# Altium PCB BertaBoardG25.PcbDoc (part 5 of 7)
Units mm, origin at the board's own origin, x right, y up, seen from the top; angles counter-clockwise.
Board outline 160 x 160 mm, 4 copper layers (Top, GND Plane, Power Plane, Bottom), stack 1.344 mm thick; 17 components, 112 nets, 2311 pads, 138 vias.
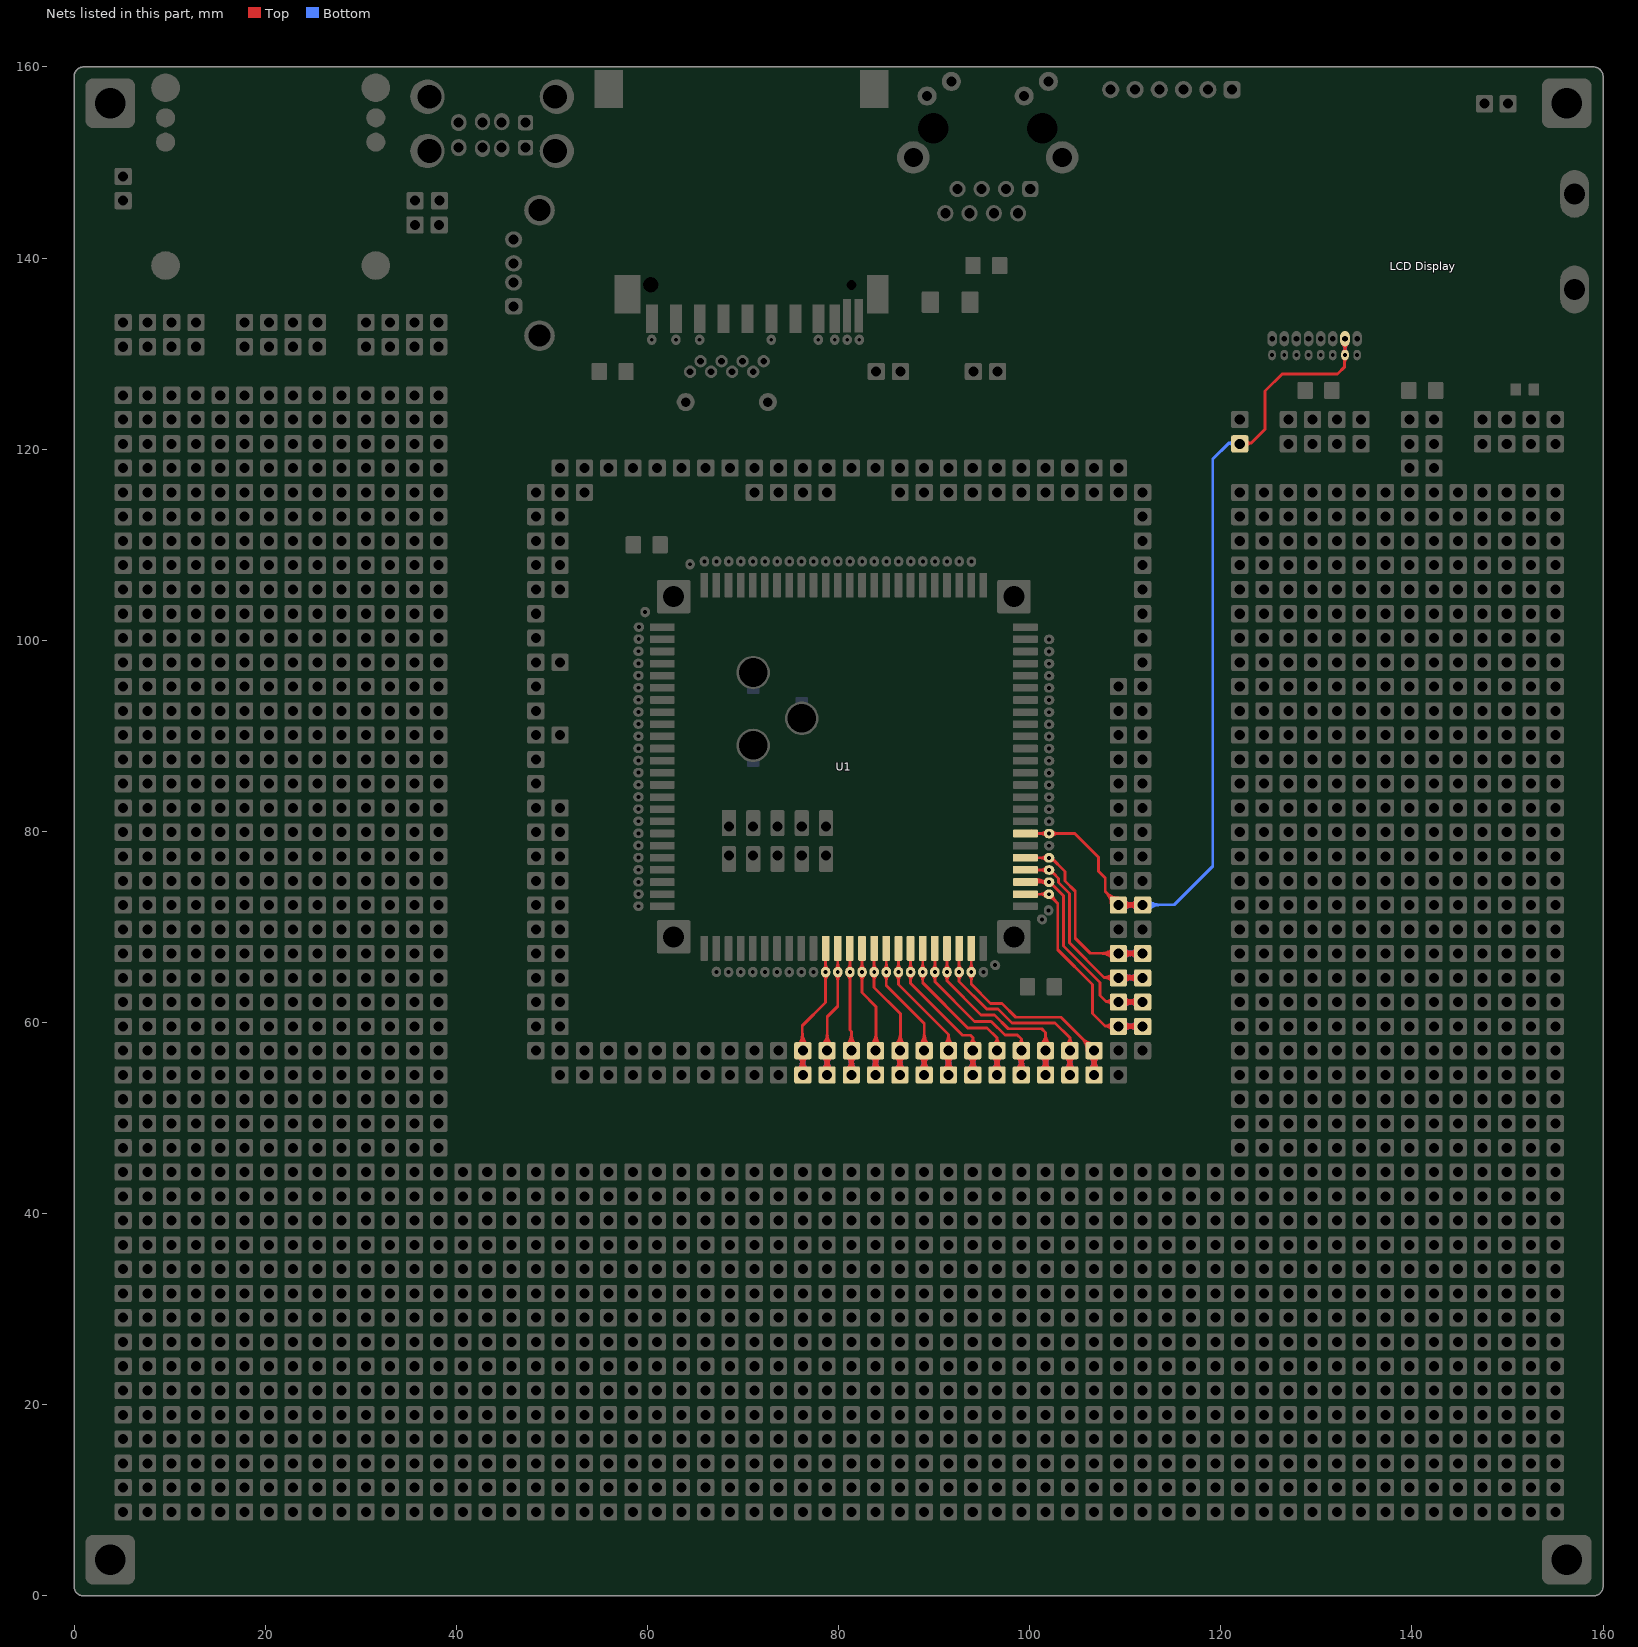
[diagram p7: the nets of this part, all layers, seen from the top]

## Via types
v1: diameter 1.5, hole 0.7, Top to Bottom, tented both sides, 54 vias
v2: diameter 1.1, hole 0.4, Top to Bottom, tented both sides, 49 vias
v3: diameter 1.9, hole 1.05, Top to Bottom, tented both sides, 17 vias
v4: diameter 1.9, hole 1.05, Top to Bottom, 16 vias
v5: diameter 0.9, hole 0.4, Top to Bottom, tented both sides, 2 vias

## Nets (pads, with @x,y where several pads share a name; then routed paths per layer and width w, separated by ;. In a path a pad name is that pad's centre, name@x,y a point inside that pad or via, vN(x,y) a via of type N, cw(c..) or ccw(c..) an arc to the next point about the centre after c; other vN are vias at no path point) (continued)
PA31: "LCD Display.7" pad.0@102.032,79.777 pad.0@109.282,72.3 pad.0@111.822,72.3 pad.0@121.982,120.56 pad.0@132.993,129.853 U1.W18 | length 142.3
  Top w0.3: U1.W18@99.551,79.785 104.716,79.785 107.201,77.3 107.201,75.83 107.901,75.13 107.901,73.72 109.291,72.33 pad.0@111.831,72.33 ; U1.W18@99.992,79.825 ccw(c100.089,79.923) U1.W18@100.089,79.785 ; U1.W18@100.204,80.037 ccw(c100.813,80.647) U1.W18@100.813,79.785 ; 101.119,79.785 cw(c101.119,78.914) pad.0@101.735,79.53 ; 101.155,79.785 ccw(c101.155,80.604) pad.0@101.735,80.025 ; pad.0@102.33,79.53 cw(c102.945,78.914) 102.945,79.785 ; pad.0@102.33,80.025 ccw(c102.909,80.604) 102.909,79.785 ; 107.973,73.647 cw(c106.626,72.3) pad.0@108.532,72.3 ; 108.069,73.552 ccw(c109.282,74.765) pad.0@109.282,73.05 ; pad.0@108.486,73.135 cw(c107.65,72.3) pad.0@108.832,72.3 ; pad.0@108.581,73.04 ccw(c109.282,73.74) pad.0@109.282,72.75 ; pad.0@109.6,71.981 cw(c110.441,71.14) 110.441,72.33 ; pad.0@109.6,72.618 ccw(c110.295,73.313) 110.295,72.33 ; pad.0@109.812,71.769 cw(c111.165,70.416) pad.0@111.165,72.33 ; pad.0@109.812,72.83 ccw(c111.02,74.037) pad.0@111.02,72.33 ; pad.0@109.938,72.33 cw(c109.938,70.416) pad.0@111.291,71.769 ; pad.0@110.084,72.33 ccw(c110.084,74.037) pad.0@111.291,72.83 ; 110.663,72.33 cw(c110.663,71.14) pad.0@111.504,71.981 ; 110.808,72.33 ccw(c110.808,73.313) pad.0@111.504,72.618 ; 110.888,72.365 ccw(c111.027,72.883) pad.0@111.459,72.566 ; pad.0@111.161,72.654 cw(c110.284,73.123) 110.541,72.163 cw(c110.691,71.605) pad.0@111.183,71.907 ; pad.0@111.168,71.932 ccw(c110.167,71.37) 110.464,72.478 ccw(c110.647,73.161) pad.0@111.217,72.743 ; pad.0@122.061,120.63 123.171,120.63 ; pad.0@122.628,120.94 ccw(c123.171,121.26) 123.171,120.63 ; pad.0@122.683,120.293 cw(c123.171,120.107) 123.171,120.63 ; 132.745,131.014 cw(c132.148,130.416) 132.993,130.416 cw(c133.838,130.416) 133.24,131.014 ; pad.0@132.816,129.526 cw(c132.466,129.176) 132.961,129.176 ; pad.0@132.816,130.179 ccw(c132.389,130.606) 132.993,130.606 ccw(c133.596,130.606) pad.0@133.17,130.179 ; 132.961,129.023 cw(c133.673,129.023) pad.0@133.17,129.526 ; pad.0@132.961,130.16 132.961,128.63 132.212,127.881 126.422,127.881 124.63,126.089 124.63,122.089 123.171,120.63 ; pad.0@132.993,130.16 132.993,131.561
  Bottom w0.3: pad.0@109.291,72.33 111.831,72.33 115.131,72.33 119.161,76.36 119.161,118.96 120.831,120.63 ; pad.0@109.6,71.981 cw(c110.441,71.14) 110.441,72.33 ; pad.0@109.6,72.618 ccw(c110.295,73.313) 110.295,72.33 ; pad.0@109.812,71.769 cw(c111.165,70.416) pad.0@111.165,72.33 ; pad.0@109.812,72.83 ccw(c111.02,74.037) pad.0@111.02,72.33 ; pad.0@109.938,72.33 cw(c109.938,70.416) pad.0@111.291,71.769 ; pad.0@110.084,72.33 ccw(c110.084,74.037) pad.0@111.291,72.83 ; 110.663,72.33 cw(c110.663,71.14) pad.0@111.504,71.981 ; 110.808,72.33 ccw(c110.808,73.313) pad.0@111.504,72.618 ; 110.888,72.365 ccw(c111.027,72.883) pad.0@111.459,72.566 ; pad.0@111.161,72.654 cw(c110.284,73.123) 110.541,72.163 cw(c110.691,71.605) pad.0@111.183,71.907 ; pad.0@111.168,71.932 ccw(c110.167,71.37) 110.464,72.478 ccw(c110.647,73.161) pad.0@111.217,72.743 ; pad.0@112.14,71.981 cw(c112.981,71.14) 112.981,72.33 ; pad.0@112.14,72.618 ccw(c112.835,73.313) 112.835,72.33 ; pad.0@112.352,71.769 cw(c113.705,70.416) 113.705,72.33 ; pad.0@112.352,72.83 ccw(c113.56,74.037) 113.56,72.33 ; pad.0@121.273,120.315 ccw(c120.831,120.163) 120.831,120.63 ; pad.0@121.325,120.921 cw(c120.831,121.193) 120.831,120.63 ; pad.0@122.061,120.63 120.831,120.63 ; 132.745,131.014 cw(c132.148,130.416) 132.993,130.416 cw(c133.838,130.416) 133.24,131.014 ; pad.0@132.816,130.179 ccw(c132.389,130.606) 132.993,130.606 ccw(c133.596,130.606) pad.0@133.17,130.179 ; pad.0@132.961,130.16 132.993,130.191 132.993,131.561
PB11: pad.0@102.032,77.237 pad.0@109.282,67.22 pad.0@111.822,67.22 U1.W20 | length 56.9
  Top w0.3: U1.W20@99.551,77.245 102.251,77.245 103.681,75.815 103.681,74.827 104.763,73.745 104.763,68.828 106.341,67.25 pad.0@111.831,67.25 ; U1.W20@99.992,77.285 ccw(c100.089,77.383) U1.W20@100.089,77.245 ; U1.W20@100.204,77.497 ccw(c100.813,78.107) U1.W20@100.813,77.245 ; pad.0@102.063,76.928 pad.0@102.472,76.928 ; 107.398,67.25 cw(c107.398,65.336) pad.0@108.751,66.689 ; 107.544,67.25 ccw(c107.544,68.957) pad.0@108.751,67.75 ; 108.123,67.25 cw(c108.123,66.06) pad.0@108.964,66.901 ; 108.268,67.25 ccw(c108.268,68.233) pad.0@108.964,67.538 ; pad.0@109.6,66.901 cw(c110.441,66.06) 110.441,67.25 ; pad.0@109.6,67.538 ccw(c110.295,68.233) 110.295,67.25 ; pad.0@109.812,66.689 cw(c111.165,65.336) pad.0@111.165,67.25 ; pad.0@109.812,67.75 ccw(c111.02,68.957) pad.0@111.02,67.25 ; pad.0@109.938,67.25 cw(c109.938,65.336) pad.0@111.291,66.689 ; pad.0@110.084,67.25 ccw(c110.084,68.957) pad.0@111.291,67.75 ; 110.663,67.25 cw(c110.663,66.06) pad.0@111.504,66.901 ; 110.808,67.25 ccw(c110.808,68.233) pad.0@111.504,67.538 ; 110.888,67.285 ccw(c111.027,67.803) pad.0@111.459,67.486 ; pad.0@111.161,67.574 cw(c110.284,68.043) 110.541,67.083 cw(c110.691,66.525) pad.0@111.183,66.827 ; pad.0@111.168,66.852 ccw(c110.167,66.29) 110.464,67.398 ccw(c110.647,68.081) pad.0@111.217,67.663 ; 101.119,77.245 cw(c101.119,76.374) 101.735,76.99 ccw(c101.119,76.374) 101.119,77.245 ; 101.155,77.245 ccw(c101.155,78.064) 101.735,77.485 cw(c101.155,78.064) 101.155,77.245
  Bottom w0.3: pad.0@109.291,67.25 pad.0@111.831,67.25 ; pad.0@109.6,66.901 cw(c110.441,66.06) 110.441,67.25 ; pad.0@109.6,67.538 ccw(c110.295,68.233) 110.295,67.25 ; pad.0@109.812,66.689 cw(c111.165,65.336) pad.0@111.165,67.25 ; pad.0@109.812,67.75 ccw(c111.02,68.957) pad.0@111.02,67.25 ; pad.0@109.938,67.25 cw(c109.938,65.336) pad.0@111.291,66.689 ; pad.0@110.084,67.25 ccw(c110.084,68.957) pad.0@111.291,67.75 ; 110.663,67.25 cw(c110.663,66.06) pad.0@111.504,66.901 ; 110.808,67.25 ccw(c110.808,68.233) pad.0@111.504,67.538 ; 110.888,67.285 ccw(c111.027,67.803) pad.0@111.459,67.486 ; pad.0@111.161,67.574 cw(c110.284,68.043) 110.541,67.083 cw(c110.691,66.525) pad.0@111.183,66.827 ; pad.0@111.168,66.852 ccw(c110.167,66.29) 110.464,67.398 ccw(c110.647,68.081) pad.0@111.217,67.663
PB12: pad.0@102.032,75.967 pad.0@109.282,64.68 pad.0@111.822,64.68 U1.W21 | length 54.5
  Top w0.3: U1.W21@99.551,75.975 101.726,75.975 102.063,75.637 102.472,75.637 ; U1.W21@99.621,76.013 ccw(c99.686,76.05) U1.W21@99.686,75.975 ; U1.W21@99.883,76.159 ccw(c100.196,76.333) U1.W21@100.196,75.975 ; U1.W21@100.165,76.209 ccw(c100.726,76.52) U1.W21@100.726,75.879 ; 101.119,75.975 cw(c101.119,75.104) pad.0@101.735,75.72 ; 101.155,75.975 ccw(c101.155,76.794) pad.0@101.735,76.215 ; pad.0@102.259,75.665 cw(c102.347,75.513) 102.472,75.637 ; pad.0@102.416,75.863 ccw(c102.63,75.796) 102.472,75.637 ; 108.364,64.71 cw(c108.364,64.043) pad.0@108.912,64.423 ; pad.0@108.665,64.252 ccw(c107.791,63.646) 107.791,64.71 ; pad.0@108.694,65.146 cw(c107.791,65.863) 107.791,64.71 ; pad.0@109.6,64.361 cw(c110.441,63.52) 110.441,64.71 ; pad.0@109.6,64.998 ccw(c110.295,65.693) 110.295,64.71 ; pad.0@109.812,64.149 cw(c111.165,62.796) pad.0@111.165,64.71 ; pad.0@109.812,65.21 ccw(c111.02,66.417) pad.0@111.02,64.71 ; pad.0@109.938,64.71 cw(c109.938,62.796) pad.0@111.291,64.149 ; pad.0@110.084,64.71 ccw(c110.084,66.417) pad.0@111.291,65.21 ; 110.663,64.71 cw(c110.663,63.52) pad.0@111.504,64.361 ; 110.808,64.71 ccw(c110.808,65.693) pad.0@111.504,64.998 ; 110.888,64.745 ccw(c111.027,65.263) pad.0@111.459,64.946 ; pad.0@111.161,65.034 cw(c110.284,65.503) 110.541,64.543 cw(c110.691,63.985) pad.0@111.183,64.287 ; pad.0@111.168,64.312 ccw(c110.167,63.75) 110.464,64.858 ccw(c110.647,65.541) pad.0@111.217,65.123 ; pad.0@111.831,64.71 107.791,64.71 ; 102.472,75.637 103.022,75.087 103.022,74.647 104.153,73.516 104.153,68.348 107.791,64.71
  Bottom w0.3: pad.0@109.291,64.71 pad.0@111.831,64.71 ; pad.0@109.6,64.361 cw(c110.441,63.52) 110.441,64.71 ; pad.0@109.6,64.998 ccw(c110.295,65.693) 110.295,64.71 ; pad.0@109.812,64.149 cw(c111.165,62.796) pad.0@111.165,64.71 ; pad.0@109.812,65.21 ccw(c111.02,66.417) pad.0@111.02,64.71 ; pad.0@109.938,64.71 cw(c109.938,62.796) pad.0@111.291,64.149 ; pad.0@110.084,64.71 ccw(c110.084,66.417) pad.0@111.291,65.21 ; 110.663,64.71 cw(c110.663,63.52) pad.0@111.504,64.361 ; 110.808,64.71 ccw(c110.808,65.693) pad.0@111.504,64.998 ; 110.888,64.745 ccw(c111.027,65.263) pad.0@111.459,64.946 ; pad.0@111.161,65.034 cw(c110.284,65.503) 110.541,64.543 cw(c110.691,63.985) pad.0@111.183,64.287 ; pad.0@111.168,64.312 ccw(c110.167,63.75) 110.464,64.858 ccw(c110.647,65.541) pad.0@111.217,65.123
PB13: pad.0@102.032,74.697 pad.0@109.282,62.14 pad.0@111.822,62.14 U1.W22 | length 56.9
  Top w0.3: U1.W22@99.267,74.805 ccw(c99.407,74.852) U1.W22@99.407,74.705 ; U1.W22@99.551,74.705 101.496,74.705 pad.0@101.642,74.559 ; U1.W22@99.551,74.901 ccw(c99.824,74.993) U1.W22@99.824,74.705 ; U1.W22@99.861,74.939 ccw(c100.268,75.076) U1.W22@100.268,74.646 ; U1.W22@100.165,74.913 ccw(c100.706,75.096) U1.W22@100.706,74.525 ; U1.W22@100.482,74.957 cw(c100.655,73.572) pad.0@101.642,74.559 ; U1.W22@100.623,74.888 cw(c100.889,73.917) pad.0@101.601,74.629 ; 101.119,74.705 cw(c101.119,73.834) pad.0@101.735,74.45 ; 101.155,74.705 ccw(c101.155,75.524) pad.0@101.735,74.945 ; pad.0@108.604,61.818 ccw(c108.001,61.532) 108.001,62.2 ; pad.0@108.656,62.553 cw(c108.001,62.984) 108.001,62.2 ; pad.0@109.201,62.2 108.001,62.2 ; pad.0@109.291,62.17 pad.0@111.831,62.17 ; pad.0@109.6,61.821 cw(c110.441,60.98) 110.441,62.17 ; pad.0@109.6,62.458 ccw(c110.295,63.153) 110.295,62.17 ; pad.0@109.812,61.609 cw(c111.165,60.256) pad.0@111.165,62.17 ; pad.0@109.812,62.67 ccw(c111.02,63.877) pad.0@111.02,62.17 ; pad.0@109.938,62.17 cw(c109.938,60.256) pad.0@111.291,61.609 ; pad.0@110.084,62.17 ccw(c110.084,63.877) pad.0@111.291,62.67 ; 110.663,62.17 cw(c110.663,60.98) pad.0@111.504,61.821 ; 110.808,62.17 ccw(c110.808,63.153) pad.0@111.504,62.458 ; 110.888,62.205 ccw(c111.027,62.723) pad.0@111.459,62.406 ; pad.0@111.161,62.494 cw(c110.284,62.963) 110.541,62.003 cw(c110.691,61.445) pad.0@111.183,61.747 ; pad.0@111.168,61.772 ccw(c110.167,61.21) 110.464,62.318 ccw(c110.647,63.001) pad.0@111.217,62.583 ; pad.0@101.642,74.559 101.642,74.609 102.205,74.609 103.544,73.27 103.544,68.027 107.361,64.21 107.361,62.839 108.001,62.2
  Bottom w0.3: pad.0@109.291,62.17 pad.0@111.831,62.17 ; pad.0@109.6,61.821 cw(c110.441,60.98) 110.441,62.17 ; pad.0@109.6,62.458 ccw(c110.295,63.153) 110.295,62.17 ; pad.0@109.812,61.609 cw(c111.165,60.256) pad.0@111.165,62.17 ; pad.0@109.812,62.67 ccw(c111.02,63.877) pad.0@111.02,62.17 ; pad.0@109.938,62.17 cw(c109.938,60.256) pad.0@111.291,61.609 ; pad.0@110.084,62.17 ccw(c110.084,63.877) pad.0@111.291,62.67 ; 110.663,62.17 cw(c110.663,60.98) pad.0@111.504,61.821 ; 110.808,62.17 ccw(c110.808,63.153) pad.0@111.504,62.458 ; 110.888,62.205 ccw(c111.027,62.723) pad.0@111.459,62.406 ; pad.0@111.161,62.494 cw(c110.284,62.963) 110.541,62.003 cw(c110.691,61.445) pad.0@111.183,61.747 ; pad.0@111.168,61.772 ccw(c110.167,61.21) 110.464,62.318 ccw(c110.647,63.001) pad.0@111.217,62.583
PB14: pad.0@102.007,73.427 pad.0@109.282,59.6 pad.0@111.822,59.6 U1.W23 | length 56.7
  Top w0.3: U1.W23@99.551,73.435 101.962,73.435 102.934,72.463 102.934,67.627 106.561,64 106.561,60.939 107.871,59.63 ; U1.W23@99.933,73.542 ccw(c100.149,73.705) U1.W23@100.149,73.435 ; U1.W23@100.191,73.643 ccw(c100.772,74.085) U1.W23@100.772,73.355 ; 101.094,73.435 cw(c101.094,72.564) pad.0@101.709,73.18 ; 101.13,73.435 ccw(c101.13,74.254) pad.0@101.709,73.675 ; pad.0@102.057,73.077 cw(c102.057,72.442) 102.506,72.891 ; pad.0@102.407,73.427 ccw(c103.462,73.427) 102.716,72.681 ; pad.0@108.647,59.201 ccw(c107.871,58.714) 107.871,59.63 ; pad.0@108.674,60.04 cw(c107.871,60.622) 107.871,59.63 ; pad.0@109.6,59.281 cw(c110.441,58.44) 110.441,59.63 ; pad.0@109.6,59.918 ccw(c110.295,60.613) 110.295,59.63 ; pad.0@109.812,59.069 cw(c111.165,57.716) pad.0@111.165,59.63 ; pad.0@109.812,60.13 ccw(c111.02,61.337) pad.0@111.02,59.63 ; pad.0@109.938,59.63 cw(c109.938,57.716) pad.0@111.291,59.069 ; pad.0@110.084,59.63 ccw(c110.084,61.337) pad.0@111.291,60.13 ; 110.663,59.63 cw(c110.663,58.44) pad.0@111.504,59.281 ; 110.808,59.63 ccw(c110.808,60.613) pad.0@111.504,59.918 ; 110.888,59.665 ccw(c111.027,60.183) pad.0@111.459,59.866 ; pad.0@111.161,59.954 cw(c110.284,60.423) 110.541,59.463 cw(c110.691,58.905) pad.0@111.183,59.207 ; pad.0@111.168,59.232 ccw(c110.167,58.67) 110.464,59.778 ccw(c110.647,60.461) pad.0@111.217,60.043 ; pad.0@111.831,59.63 107.871,59.63
  Bottom w0.3: pad.0@109.291,59.63 pad.0@111.831,59.63 ; pad.0@109.6,59.281 cw(c110.441,58.44) 110.441,59.63 ; pad.0@109.6,59.918 ccw(c110.295,60.613) 110.295,59.63 ; pad.0@109.812,59.069 cw(c111.165,57.716) pad.0@111.165,59.63 ; pad.0@109.812,60.13 ccw(c111.02,61.337) pad.0@111.02,59.63 ; pad.0@109.938,59.63 cw(c109.938,57.716) pad.0@111.291,59.069 ; pad.0@110.084,59.63 ccw(c110.084,61.337) pad.0@111.291,60.13 ; 110.663,59.63 cw(c110.663,58.44) pad.0@111.504,59.281 ; 110.808,59.63 ccw(c110.808,60.613) pad.0@111.504,59.918 ; 110.888,59.665 ccw(c111.027,60.183) pad.0@111.459,59.866 ; pad.0@111.161,59.954 cw(c110.284,60.423) 110.541,59.463 cw(c110.691,58.905) pad.0@111.183,59.207 ; pad.0@111.168,59.232 ccw(c110.167,58.67) 110.464,59.778 ccw(c110.647,60.461) pad.0@111.217,60.043
PC0: pad.0@93.889,65.279 pad.0@106.742,54.52 pad.0@106.742,57.06 U1.N2 | length 59.3
  Top w0.3: pad.0@93.641,64.981 cw(c93.038,64.378) 93.891,64.377 ; pad.0@93.641,65.576 ccw(c93.038,66.18) 93.891,66.18 ; U1.N2@93.709,67.193 cw(c93.271,66.754) U1.N2@93.891,66.754 ; 93.891,64.39 cw(c94.727,64.39) pad.0@94.136,64.981 ; 93.891,66.167 ccw(c94.728,66.167) pad.0@94.136,65.576 ; U1.N2@93.891,66.778 cw(c94.478,66.778) U1.N2@94.063,67.193 ; U1.N2@93.961,67.06 93.891,66.99 93.891,64.03 95.911,62.01 97.091,62.01 98.541,60.56 103.281,60.56 106.751,57.09 pad.0@106.751,54.55 ; 105.433,58.407 cw(c104.086,57.06) pad.0@105.992,57.06 ; 105.529,58.312 ccw(c106.742,59.525) pad.0@106.742,57.81 ; pad.0@105.946,57.895 cw(c105.11,57.06) pad.0@106.292,57.06 ; pad.0@106.041,57.8 ccw(c106.742,58.5) pad.0@106.742,57.51 ; pad.0@106.211,55.05 ccw(c104.908,56.353) pad.0@106.751,56.353 ; pad.0@106.211,56.529 cw(c104.908,55.226) pad.0@106.751,55.226 ; pad.0@106.331,56.432 cw(c105.991,55.913) 106.59,55.753 cw(c107.601,55.482) pad.0@107.101,56.401 ; pad.0@106.379,56.403 cw(c105.849,55.445) 106.906,55.729 cw(c107.544,55.9) pad.0@107.168,56.443 ; pad.0@106.424,54.838 ccw(c105.633,55.629) 106.751,55.629 ; pad.0@106.424,56.741 cw(c105.633,55.95) 106.751,55.95 ; pad.0@106.495,56.683 cw(c106.23,56.278) 106.698,56.153 ; pad.0@106.751,55.272 cw(c108.53,55.272) pad.0@107.272,56.529 ; 106.751,55.583 ccw(c107.805,55.583) pad.0@107.06,54.838 ; 106.751,55.996 cw(c107.805,55.996) pad.0@107.06,56.741 ; pad.0@106.751,56.307 ccw(c108.53,56.307) pad.0@107.272,55.05 ; 106.796,56.14 cw(c107.287,56.272) pad.0@106.998,56.69
  Bottom w0.3: pad.0@106.211,55.05 ccw(c104.908,56.353) pad.0@106.751,56.353 ; pad.0@106.211,56.529 cw(c104.908,55.226) pad.0@106.751,55.226 ; pad.0@106.331,56.432 cw(c105.991,55.913) 106.59,55.753 cw(c107.601,55.482) pad.0@107.101,56.401 ; pad.0@106.379,56.403 cw(c105.849,55.445) 106.906,55.729 cw(c107.544,55.9) pad.0@107.168,56.443 ; pad.0@106.424,54.838 ccw(c105.633,55.629) 106.751,55.629 ; pad.0@106.424,56.741 cw(c105.633,55.95) 106.751,55.95 ; pad.0@106.495,56.683 cw(c106.23,56.278) 106.698,56.153 ; pad.0@106.751,54.55 pad.0@106.751,57.09 ; pad.0@106.751,55.272 cw(c108.53,55.272) pad.0@107.272,56.529 ; 106.751,55.583 ccw(c107.805,55.583) pad.0@107.06,54.838 ; 106.751,55.996 cw(c107.805,55.996) pad.0@107.06,56.741 ; pad.0@106.751,56.307 ccw(c108.53,56.307) pad.0@107.272,55.05 ; 106.796,56.14 cw(c107.287,56.272) pad.0@106.998,56.69
PC1: pad.0@92.619,65.279 pad.0@104.202,54.52 pad.0@104.202,57.06 U1.N3 | length 56.5
  Top w0.3: pad.0@92.371,64.981 cw(c91.78,64.39) 92.616,64.39 ; pad.0@92.371,65.576 ccw(c91.78,66.167) 92.616,66.167 ; U1.N3@92.439,67.193 cw(c92.013,66.766) 92.616,66.766 cw(c93.22,66.766) U1.N3@92.793,67.193 ; 92.616,64.377 cw(c93.47,64.377) pad.0@92.866,64.981 ; 92.616,66.18 ccw(c93.47,66.18) pad.0@92.866,65.576 ; U1.N3@92.616,67.77 92.616,64.305 95.501,61.42 96.701,61.42 98.161,59.96 102.661,59.96 104.211,58.41 ; pad.0@103.671,55.05 ccw(c102.368,56.353) pad.0@104.211,56.353 ; pad.0@103.671,56.529 cw(c102.368,55.226) pad.0@104.211,55.226 ; pad.0@103.791,56.432 cw(c103.451,55.913) 104.05,55.753 cw(c105.061,55.482) pad.0@104.561,56.401 ; pad.0@103.812,57.701 ccw(c103.381,58.41) 104.211,58.41 ; pad.0@103.839,56.403 cw(c103.309,55.445) 104.366,55.729 cw(c105.004,55.9) pad.0@104.628,56.443 ; pad.0@103.884,54.838 ccw(c103.093,55.629) 104.211,55.629 ; pad.0@103.884,56.741 cw(c103.093,55.95) 104.211,55.95 ; pad.0@103.955,56.683 cw(c103.69,56.278) 104.158,56.153 ; pad.0@104.211,54.55 104.211,58.41 ; pad.0@104.211,55.272 cw(c105.99,55.272) pad.0@104.732,56.529 ; 104.211,55.583 ccw(c105.265,55.583) pad.0@104.52,54.838 ; 104.211,55.996 cw(c105.265,55.996) pad.0@104.52,56.741 ; pad.0@104.211,56.307 ccw(c105.99,56.307) pad.0@104.732,55.05 ; 104.256,56.14 cw(c104.747,56.272) pad.0@104.458,56.69 ; pad.0@104.605,57.692 cw(c105.062,58.41) 104.211,58.41
  Bottom w0.3: pad.0@103.671,55.05 ccw(c102.368,56.353) pad.0@104.211,56.353 ; pad.0@103.671,56.529 cw(c102.368,55.226) pad.0@104.211,55.226 ; pad.0@103.791,56.432 cw(c103.451,55.913) 104.05,55.753 cw(c105.061,55.482) pad.0@104.561,56.401 ; pad.0@103.839,56.403 cw(c103.309,55.445) 104.366,55.729 cw(c105.004,55.9) pad.0@104.628,56.443 ; pad.0@103.884,54.838 ccw(c103.093,55.629) 104.211,55.629 ; pad.0@103.884,56.741 cw(c103.093,55.95) 104.211,55.95 ; pad.0@103.955,56.683 cw(c103.69,56.278) 104.158,56.153 ; pad.0@104.211,54.55 pad.0@104.211,57.09 ; pad.0@104.211,55.272 cw(c105.99,55.272) pad.0@104.732,56.529 ; 104.211,55.583 ccw(c105.265,55.583) pad.0@104.52,54.838 ; 104.211,55.996 cw(c105.265,55.996) pad.0@104.52,56.741 ; pad.0@104.211,56.307 ccw(c105.99,56.307) pad.0@104.732,55.05 ; 104.256,56.14 cw(c104.747,56.272) pad.0@104.458,56.69
PC2: pad.0@91.349,65.279 pad.0@101.662,54.52 pad.0@101.662,57.06 U1.N4 | length 58.4
  Top w0.3: pad.0@91.101,64.981 cw(c90.51,64.39) 91.346,64.39 ; pad.0@91.101,65.576 ccw(c90.51,66.167) 91.346,66.167 ; U1.N4@91.169,67.193 cw(c90.743,66.766) 91.346,66.766 cw(c91.95,66.766) U1.N4@91.523,67.193 ; 91.346,64.377 cw(c92.2,64.377) pad.0@91.596,64.981 ; 91.346,66.18 ccw(c92.2,66.18) pad.0@91.596,65.576 ; U1.N4@91.346,67.77 91.346,64.375 94.911,60.81 96.311,60.81 97.761,59.36 101.261,59.36 101.671,58.95 pad.0@101.671,54.55 ; pad.0@101.131,55.05 ccw(c99.828,56.353) pad.0@101.671,56.353 ; pad.0@101.131,56.529 cw(c99.828,55.226) pad.0@101.671,55.226 ; pad.0@101.131,57.59 ccw(c99.828,58.893) 101.671,58.893 ; pad.0@101.251,56.432 cw(c100.911,55.913) 101.51,55.753 cw(c102.521,55.482) pad.0@102.021,56.401 ; pad.0@101.299,56.403 cw(c100.769,55.445) 101.826,55.729 cw(c102.464,55.9) pad.0@102.088,56.443 ; pad.0@101.344,54.838 ccw(c100.553,55.629) 101.671,55.629 ; pad.0@101.344,56.741 cw(c100.553,55.95) 101.671,55.95 ; pad.0@101.344,57.378 ccw(c100.553,58.169) 101.671,58.169 ; pad.0@101.415,56.683 cw(c101.15,56.278) 101.618,56.153 ; pad.0@101.671,55.272 cw(c103.45,55.272) pad.0@102.192,56.529 ; 101.671,55.583 ccw(c102.725,55.583) pad.0@101.98,54.838 ; 101.671,55.996 cw(c102.725,55.996) pad.0@101.98,56.741 ; pad.0@101.671,56.307 ccw(c103.45,56.307) pad.0@102.192,55.05 ; 101.671,58.123 ccw(c102.725,58.123) pad.0@101.98,57.378 ; 101.671,58.847 ccw(c103.45,58.847) pad.0@102.192,57.59 ; 101.716,56.14 cw(c102.207,56.272) pad.0@101.918,56.69
  Bottom w0.3: pad.0@101.131,55.05 ccw(c99.828,56.353) pad.0@101.671,56.353 ; pad.0@101.131,56.529 cw(c99.828,55.226) pad.0@101.671,55.226 ; pad.0@101.251,56.432 cw(c100.911,55.913) 101.51,55.753 cw(c102.521,55.482) pad.0@102.021,56.401 ; pad.0@101.299,56.403 cw(c100.769,55.445) 101.826,55.729 cw(c102.464,55.9) pad.0@102.088,56.443 ; pad.0@101.344,54.838 ccw(c100.553,55.629) 101.671,55.629 ; pad.0@101.344,56.741 cw(c100.553,55.95) 101.671,55.95 ; pad.0@101.415,56.683 cw(c101.15,56.278) 101.618,56.153 ; pad.0@101.671,54.55 pad.0@101.671,57.09 ; pad.0@101.671,55.272 cw(c103.45,55.272) pad.0@102.192,56.529 ; 101.671,55.583 ccw(c102.725,55.583) pad.0@101.98,54.838 ; 101.671,55.996 cw(c102.725,55.996) pad.0@101.98,56.741 ; pad.0@101.671,56.307 ccw(c103.45,56.307) pad.0@102.192,55.05 ; 101.716,56.14 cw(c102.207,56.272) pad.0@101.918,56.69
PC3: pad.0@90.079,65.279 pad.0@99.122,54.52 pad.0@99.122,57.06 U1.N5 | length 53.5
  Top w0.3: pad.0@89.831,64.981 cw(c89.24,64.39) 90.076,64.39 ; pad.0@89.831,65.576 ccw(c89.24,66.167) 90.076,66.167 ; U1.N5@89.899,67.193 cw(c89.473,66.766) 90.076,66.766 cw(c90.68,66.766) U1.N5@90.253,67.193 ; 90.076,64.377 cw(c90.93,64.377) pad.0@90.326,64.981 ; 90.076,66.18 ccw(c90.93,66.18) pad.0@90.326,65.576 ; U1.N5@90.076,67.77 90.076,64.265 94.211,60.13 95.971,60.13 97.401,58.7 98.701,58.7 99.131,58.269 ; pad.0@98.591,55.05 ccw(c97.288,56.353) pad.0@99.131,56.353 ; pad.0@98.591,56.529 cw(c97.288,55.226) pad.0@99.131,55.226 ; pad.0@98.711,56.432 cw(c98.371,55.913) 98.97,55.753 cw(c99.981,55.482) pad.0@99.481,56.401 ; pad.0@98.759,56.403 cw(c98.229,55.445) 99.286,55.729 cw(c99.924,55.9) pad.0@99.548,56.443 ; pad.0@98.796,57.735 ccw(c98.538,58.269) 99.131,58.269 ; pad.0@98.804,54.838 ccw(c98.013,55.629) 99.131,55.629 ; pad.0@98.804,56.741 cw(c98.013,55.95) 99.131,55.95 ; pad.0@98.875,56.683 cw(c98.61,56.278) 99.078,56.153 ; pad.0@99.131,54.55 99.131,58.269 ; pad.0@99.131,55.272 cw(c100.91,55.272) pad.0@99.652,56.529 ; 99.131,55.583 ccw(c100.185,55.583) pad.0@99.44,54.838 ; 99.131,55.996 cw(c100.185,55.996) pad.0@99.44,56.741 ; pad.0@99.131,56.307 ccw(c100.91,56.307) pad.0@99.652,55.05 ; 99.176,56.14 cw(c99.667,56.272) pad.0@99.378,56.69 ; pad.0@99.463,57.728 cw(c99.739,58.269) 99.131,58.269
  Bottom w0.3: pad.0@98.591,55.05 ccw(c97.288,56.353) pad.0@99.131,56.353 ; pad.0@98.591,56.529 cw(c97.288,55.226) pad.0@99.131,55.226 ; pad.0@98.711,56.432 cw(c98.371,55.913) 98.97,55.753 cw(c99.981,55.482) pad.0@99.481,56.401 ; pad.0@98.759,56.403 cw(c98.229,55.445) 99.286,55.729 cw(c99.924,55.9) pad.0@99.548,56.443 ; pad.0@98.804,54.838 ccw(c98.013,55.629) 99.131,55.629 ; pad.0@98.804,56.741 cw(c98.013,55.95) 99.131,55.95 ; pad.0@98.875,56.683 cw(c98.61,56.278) 99.078,56.153 ; pad.0@99.131,54.55 pad.0@99.131,57.09 ; pad.0@99.131,55.272 cw(c100.91,55.272) pad.0@99.652,56.529 ; 99.131,55.583 ccw(c100.185,55.583) pad.0@99.44,54.838 ; 99.131,55.996 cw(c100.185,55.996) pad.0@99.44,56.741 ; pad.0@99.131,56.307 ccw(c100.91,56.307) pad.0@99.652,55.05 ; 99.176,56.14 cw(c99.667,56.272) pad.0@99.378,56.69
PC4: pad.0@88.809,65.279 pad.0@96.582,54.52 pad.0@96.582,57.06 U1.N6 | length 52.8
  Top w0.3: pad.0@88.561,64.981 cw(c87.97,64.39) 88.806,64.39 ; pad.0@88.561,65.576 ccw(c87.97,66.167) 88.806,66.167 ; U1.N6@88.629,67.193 cw(c88.203,66.766) 88.806,66.766 cw(c89.41,66.766) U1.N6@88.983,67.193 ; 88.806,64.377 cw(c89.66,64.377) pad.0@89.056,64.981 ; 88.806,66.18 ccw(c89.66,66.18) pad.0@89.056,65.576 ; U1.N6@88.806,67.77 88.806,64.165 93.521,59.45 95.551,59.45 96.591,58.409 ; pad.0@96.051,55.05 ccw(c94.748,56.353) pad.0@96.591,56.353 ; pad.0@96.051,56.529 cw(c94.748,55.226) pad.0@96.591,55.226 ; pad.0@96.171,56.432 cw(c95.831,55.913) 96.43,55.753 cw(c97.441,55.482) pad.0@96.941,56.401 ; pad.0@96.192,57.701 ccw(c95.762,58.409) 96.591,58.409 ; pad.0@96.219,56.403 cw(c95.689,55.445) 96.746,55.729 cw(c97.384,55.9) pad.0@97.008,56.443 ; pad.0@96.264,54.838 ccw(c95.473,55.629) 96.591,55.629 ; pad.0@96.264,56.741 cw(c95.473,55.95) 96.591,55.95 ; pad.0@96.335,56.683 cw(c96.07,56.278) 96.538,56.153 ; pad.0@96.591,54.55 96.591,58.409 ; pad.0@96.591,55.272 cw(c98.37,55.272) pad.0@97.112,56.529 ; 96.591,55.583 ccw(c97.645,55.583) pad.0@96.9,54.838 ; 96.591,55.996 cw(c97.645,55.996) pad.0@96.9,56.741 ; pad.0@96.591,56.307 ccw(c98.37,56.307) pad.0@97.112,55.05 ; 96.636,56.14 cw(c97.127,56.272) pad.0@96.838,56.69 ; pad.0@96.985,57.692 cw(c97.441,58.409) 96.591,58.409
  Bottom w0.3: pad.0@96.051,55.05 ccw(c94.748,56.353) pad.0@96.591,56.353 ; pad.0@96.051,56.529 cw(c94.748,55.226) pad.0@96.591,55.226 ; pad.0@96.171,56.432 cw(c95.831,55.913) 96.43,55.753 cw(c97.441,55.482) pad.0@96.941,56.401 ; pad.0@96.219,56.403 cw(c95.689,55.445) 96.746,55.729 cw(c97.384,55.9) pad.0@97.008,56.443 ; pad.0@96.264,54.838 ccw(c95.473,55.629) 96.591,55.629 ; pad.0@96.264,56.741 cw(c95.473,55.95) 96.591,55.95 ; pad.0@96.335,56.683 cw(c96.07,56.278) 96.538,56.153 ; pad.0@96.591,54.55 pad.0@96.591,57.09 ; pad.0@96.591,55.272 cw(c98.37,55.272) pad.0@97.112,56.529 ; 96.591,55.583 ccw(c97.645,55.583) pad.0@96.9,54.838 ; 96.591,55.996 cw(c97.645,55.996) pad.0@96.9,56.741 ; pad.0@96.591,56.307 ccw(c98.37,56.307) pad.0@97.112,55.05 ; 96.636,56.14 cw(c97.127,56.272) pad.0@96.838,56.69
PC5: pad.0@87.539,65.279 pad.0@94.042,54.52 pad.0@94.042,57.06 U1.N7 | length 51.6
  Top w0.3: pad.0@87.291,64.981 cw(c86.7,64.39) 87.536,64.39 ; pad.0@87.291,65.576 ccw(c86.7,66.167) 87.536,66.167 ; U1.N7@87.359,67.193 cw(c86.933,66.766) 87.536,66.766 cw(c88.14,66.766) U1.N7@87.713,67.193 ; 87.536,64.377 cw(c88.39,64.377) pad.0@87.786,64.981 ; 87.536,66.18 ccw(c88.39,66.18) pad.0@87.786,65.576 ; U1.N7@87.536,67.77 87.536,64.115 92.971,58.68 93.811,58.68 94.051,58.44 ; pad.0@93.511,55.05 ccw(c92.184,56.377) pad.0@94.061,56.377 ; pad.0@93.511,56.529 cw(c92.184,55.202) pad.0@94.061,55.202 ; pad.0@93.64,56.426 cw(c93.319,55.921) 93.897,55.766 cw(c94.884,55.501) pad.0@94.398,56.4 ; pad.0@93.64,57.693 ccw(c93.168,58.44) 94.051,58.44 ; pad.0@93.677,56.404 cw(c93.131,55.426) 94.213,55.716 cw(c94.872,55.893) pad.0@94.477,56.449 ; pad.0@93.724,54.838 ccw(c92.908,55.653) 94.061,55.653 ; pad.0@93.724,56.741 cw(c92.908,55.926) 94.061,55.926 ; pad.0@93.801,56.68 cw(c93.548,56.282) pad.0@94.003,56.16 ; pad.0@94.051,57.09 94.051,58.44 ; pad.0@94.061,54.52 pad.0@94.061,57.06 ; pad.0@94.061,55.296 cw(c95.806,55.296) pad.0@94.572,56.529 ; 94.061,55.559 ccw(c95.081,55.559) pad.0@94.36,54.838 ; 94.061,56.02 cw(c95.081,56.02) pad.0@94.36,56.741 ; pad.0@94.061,56.283 ccw(c95.806,56.283) pad.0@94.572,55.05 ; 94.101,56.133 cw(c94.605,56.268) pad.0@94.303,56.693 ; pad.0@94.456,57.685 cw(c94.957,58.44) 94.051,58.44
  Bottom w0.3: pad.0@93.511,55.05 ccw(c92.184,56.377) pad.0@94.061,56.377 ; pad.0@93.511,56.529 cw(c92.184,55.202) pad.0@94.061,55.202 ; pad.0@93.64,56.426 cw(c93.319,55.921) 93.897,55.766 cw(c94.884,55.501) pad.0@94.398,56.4 ; pad.0@93.677,56.404 cw(c93.131,55.426) 94.213,55.716 cw(c94.872,55.893) pad.0@94.477,56.449 ; pad.0@93.724,54.838 ccw(c92.908,55.653) 94.061,55.653 ; pad.0@93.724,56.741 cw(c92.908,55.926) 94.061,55.926 ; pad.0@93.801,56.68 cw(c93.548,56.282) pad.0@94.003,56.16 ; pad.0@94.061,54.52 pad.0@94.061,57.06 ; pad.0@94.061,55.296 cw(c95.806,55.296) pad.0@94.572,56.529 ; 94.061,55.559 ccw(c95.081,55.559) pad.0@94.36,54.838 ; 94.061,56.02 cw(c95.081,56.02) pad.0@94.36,56.741 ; pad.0@94.061,56.283 ccw(c95.806,56.283) pad.0@94.572,55.05 ; 94.101,56.133 cw(c94.605,56.268) pad.0@94.303,56.693
PC6: pad.0@86.269,65.279 pad.0@91.502,54.52 pad.0@91.502,57.06 U1.N8 | length 52.9
  Top w0.3: pad.0@86.021,64.981 cw(c85.43,64.39) 86.266,64.39 ; pad.0@86.021,65.576 ccw(c85.43,66.167) 86.266,66.167 ; U1.N8@86.089,67.193 cw(c85.663,66.766) 86.266,66.766 cw(c86.87,66.766) U1.N8@86.443,67.193 ; 86.266,64.377 cw(c87.12,64.377) pad.0@86.516,64.981 ; 86.266,66.18 ccw(c87.12,66.18) pad.0@86.516,65.576 ; U1.N8@86.266,67.77 86.266,63.985 91.511,58.74 ; pad.0@90.971,55.05 ccw(c89.692,56.329) pad.0@91.501,56.329 ; pad.0@90.971,56.529 cw(c89.692,55.25) pad.0@91.501,55.25 ; pad.0@91.006,57.623 ccw(c90.023,58.74) 91.511,58.74 ; pad.0@91.082,56.438 cw(c90.724,55.906) 91.343,55.74 cw(c92.379,55.463) pad.0@91.863,56.402 ; pad.0@91.141,56.402 cw(c90.627,55.465) 91.659,55.742 cw(c92.276,55.907) pad.0@91.92,56.437 ; pad.0@91.184,54.838 ccw(c90.417,55.605) 91.501,55.605 ; pad.0@91.184,56.741 cw(c90.417,55.975) 91.501,55.975 ; pad.0@91.204,57.397 ccw(c90.607,58.076) 91.511,58.076 ; pad.0@91.25,56.686 cw(c90.973,56.275) 91.452,56.146 ; pad.0@91.501,54.58 pad.0@91.501,57.12 ; pad.0@91.501,55.248 cw(c93.314,55.248) pad.0@92.032,56.529 ; 91.501,55.607 ccw(c92.589,55.607) pad.0@91.82,54.838 ; 91.501,55.972 cw(c92.589,55.972) pad.0@91.82,56.741 ; pad.0@91.501,56.332 ccw(c93.314,56.332) pad.0@92.032,55.05 ; pad.0@91.511,57.09 91.511,58.74 ; 91.511,58.059 ccw(c92.415,58.059) pad.0@91.805,57.392 ; 91.551,56.147 cw(c92.029,56.275) pad.0@91.753,56.686 ; pad.0@92.008,57.613 cw(c93.037,58.74) 91.511,58.74
  Bottom w0.3: pad.0@90.971,55.05 ccw(c89.692,56.329) pad.0@91.501,56.329 ; pad.0@90.971,56.529 cw(c89.692,55.25) pad.0@91.501,55.25 ; pad.0@91.082,56.438 cw(c90.724,55.906) 91.343,55.74 cw(c92.379,55.463) pad.0@91.863,56.402 ; pad.0@91.141,56.402 cw(c90.627,55.465) 91.659,55.742 cw(c92.276,55.907) pad.0@91.92,56.437 ; pad.0@91.184,54.838 ccw(c90.417,55.605) 91.501,55.605 ; pad.0@91.184,56.741 cw(c90.417,55.975) 91.501,55.975 ; pad.0@91.25,56.686 cw(c90.973,56.275) 91.452,56.146 ; pad.0@91.501,54.58 pad.0@91.501,57.12 ; pad.0@91.501,55.248 cw(c93.314,55.248) pad.0@92.032,56.529 ; 91.501,55.607 ccw(c92.589,55.607) pad.0@91.82,54.838 ; 91.501,55.972 cw(c92.589,55.972) pad.0@91.82,56.741 ; pad.0@91.501,56.332 ccw(c93.314,56.332) pad.0@92.032,55.05 ; 91.551,56.147 cw(c92.029,56.275) pad.0@91.753,56.686
PC7: pad.0@84.999,65.279 pad.0@88.962,54.52 pad.0@88.962,57.06 U1.N9 | length 52.9
  Top w0.3: pad.0@84.751,64.981 cw(c84.16,64.39) 84.996,64.39 ; pad.0@84.751,65.576 ccw(c84.16,66.167) 84.996,66.167 ; U1.N9@84.819,67.193 cw(c84.393,66.766) 84.996,66.766 cw(c85.6,66.766) U1.N9@85.173,67.193 ; 84.996,64.377 cw(c85.85,64.377) pad.0@85.246,64.981 ; 84.996,66.18 ccw(c85.85,66.18) pad.0@85.246,65.576 ; U1.N9@84.996,67.77 84.996,63.875 88.971,59.9 pad.0@88.971,54.55 ; pad.0@88.431,55.05 ccw(c87.128,56.353) pad.0@88.971,56.353 ; pad.0@88.431,56.529 cw(c87.128,55.226) pad.0@88.971,55.226 ; pad.0@88.431,57.59 ccw(c87.128,58.893) 88.971,58.893 ; pad.0@88.551,56.432 cw(c88.211,55.913) 88.81,55.753 cw(c89.821,55.482) pad.0@89.321,56.401 ; pad.0@88.599,56.403 cw(c88.069,55.445) 89.126,55.729 cw(c89.764,55.9) pad.0@89.388,56.443 ; pad.0@88.644,54.838 ccw(c87.853,55.629) 88.971,55.629 ; pad.0@88.644,56.741 cw(c87.853,55.95) 88.971,55.95 ; pad.0@88.644,57.378 ccw(c87.853,58.169) 88.971,58.169 ; pad.0@88.715,56.683 cw(c88.45,56.278) 88.918,56.153 ; pad.0@88.971,55.272 cw(c90.75,55.272) pad.0@89.492,56.529 ; 88.971,55.583 ccw(c90.025,55.583) pad.0@89.28,54.838 ; 88.971,55.996 cw(c90.025,55.996) pad.0@89.28,56.741 ; pad.0@88.971,56.307 ccw(c90.75,56.307) pad.0@89.492,55.05 ; 88.971,58.123 ccw(c90.025,58.123) pad.0@89.28,57.378 ; 88.971,58.847 ccw(c90.75,58.847) pad.0@89.492,57.59 ; 89.016,56.14 cw(c89.507,56.272) pad.0@89.218,56.69
  Bottom w0.3: pad.0@88.431,55.05 ccw(c87.128,56.353) pad.0@88.971,56.353 ; pad.0@88.431,56.529 cw(c87.128,55.226) pad.0@88.971,55.226 ; pad.0@88.551,56.432 cw(c88.211,55.913) 88.81,55.753 cw(c89.821,55.482) pad.0@89.321,56.401 ; pad.0@88.599,56.403 cw(c88.069,55.445) 89.126,55.729 cw(c89.764,55.9) pad.0@89.388,56.443 ; pad.0@88.644,54.838 ccw(c87.853,55.629) 88.971,55.629 ; pad.0@88.644,56.741 cw(c87.853,55.95) 88.971,55.95 ; pad.0@88.715,56.683 cw(c88.45,56.278) 88.918,56.153 ; pad.0@88.971,54.55 pad.0@88.971,57.09 ; pad.0@88.971,55.272 cw(c90.75,55.272) pad.0@89.492,56.529 ; 88.971,55.583 ccw(c90.025,55.583) pad.0@89.28,54.838 ; 88.971,55.996 cw(c90.025,55.996) pad.0@89.28,56.741 ; pad.0@88.971,56.307 ccw(c90.75,56.307) pad.0@89.492,55.05 ; 89.016,56.14 cw(c89.507,56.272) pad.0@89.218,56.69
PC8: pad.0@83.729,65.279 pad.0@86.422,54.52 pad.0@86.422,57.06 U1.N10 | length 51.7
  Top w0.3: pad.0@83.481,64.981 cw(c82.89,64.39) 83.726,64.39 ; pad.0@83.481,65.576 ccw(c82.89,66.167) 83.726,66.167 ; U1.N10@83.549,67.193 cw(c83.123,66.766) 83.726,66.766 cw(c84.33,66.766) U1.N10@83.903,67.193 ; 83.726,64.377 cw(c84.58,64.377) pad.0@83.976,64.981 ; 83.726,66.18 ccw(c84.58,66.18) pad.0@83.976,65.576 ; U1.N10@83.726,67.77 83.726,63.685 86.501,60.91 86.501,57.159 86.431,57.09 pad.0@86.431,54.55 ; pad.0@85.891,55.05 ccw(c84.588,56.353) pad.0@86.431,56.353 ; pad.0@85.891,56.529 cw(c84.588,55.226) pad.0@86.431,55.226 ; pad.0@85.891,57.59 ccw(c84.421,59.061) 86.501,59.061 ; pad.0@86.011,56.432 cw(c85.671,55.913) 86.27,55.753 cw(c87.281,55.482) pad.0@86.781,56.401 ; pad.0@86.059,56.403 cw(c85.529,55.445) 86.586,55.729 cw(c87.224,55.9) pad.0@86.848,56.443 ; pad.0@86.104,54.838 ccw(c85.313,55.629) 86.431,55.629 ; pad.0@86.104,56.741 cw(c85.313,55.95) 86.431,55.95 ; pad.0@86.104,57.378 ccw(c85.145,58.336) 86.501,58.336 ; pad.0@86.175,56.683 cw(c85.91,56.278) 86.378,56.153 ; pad.0@86.431,55.272 cw(c88.21,55.272) pad.0@86.952,56.529 ; 86.431,55.583 ccw(c87.485,55.583) pad.0@86.74,54.838 ; 86.431,55.996 cw(c87.485,55.996) pad.0@86.74,56.741 ; pad.0@86.431,56.307 ccw(c88.21,56.307) pad.0@86.952,55.05 ; 86.476,56.14 cw(c86.967,56.272) pad.0@86.678,56.69 ; 86.501,58.68 ccw(c88.042,58.68) pad.0@86.952,57.59
  Bottom w0.3: pad.0@85.891,55.05 ccw(c84.588,56.353) pad.0@86.431,56.353 ; pad.0@85.891,56.529 cw(c84.588,55.226) pad.0@86.431,55.226 ; pad.0@86.011,56.432 cw(c85.671,55.913) 86.27,55.753 cw(c87.281,55.482) pad.0@86.781,56.401 ; pad.0@86.059,56.403 cw(c85.529,55.445) 86.586,55.729 cw(c87.224,55.9) pad.0@86.848,56.443 ; pad.0@86.104,54.838 ccw(c85.313,55.629) 86.431,55.629 ; pad.0@86.104,56.741 cw(c85.313,55.95) 86.431,55.95 ; pad.0@86.175,56.683 cw(c85.91,56.278) 86.378,56.153 ; pad.0@86.431,54.55 pad.0@86.431,57.09 ; pad.0@86.431,55.272 cw(c88.21,55.272) pad.0@86.952,56.529 ; 86.431,55.583 ccw(c87.485,55.583) pad.0@86.74,54.838 ; 86.431,55.996 cw(c87.485,55.996) pad.0@86.74,56.741 ; pad.0@86.431,56.307 ccw(c88.21,56.307) pad.0@86.952,55.05 ; 86.476,56.14 cw(c86.967,56.272) pad.0@86.678,56.69
PC9: pad.0@82.459,65.279 pad.0@83.882,54.52 pad.0@83.882,57.06 U1.N11 | length 50.6
  Top w0.3: pad.0@82.211,64.981 cw(c81.62,64.39) 82.456,64.39 ; pad.0@82.211,65.576 ccw(c81.62,66.167) 82.456,66.167 ; U1.N11@82.279,67.193 cw(c81.853,66.766) 82.456,66.766 cw(c83.06,66.766) U1.N11@82.633,67.193 ; 82.456,64.377 cw(c83.31,64.377) pad.0@82.706,64.981 ; 82.456,66.18 ccw(c83.31,66.18) pad.0@82.706,65.576 ; U1.N11@82.456,67.77 82.456,63.144 83.901,61.7 83.901,57.099 pad.0@83.891,57.09 ; pad.0@83.351,55.05 ccw(c82.121,56.281) pad.0@83.861,56.281 ; pad.0@83.351,56.529 cw(c82.121,55.299) pad.0@83.861,55.299 ; pad.0@83.351,57.59 ccw(c82.026,58.916) 83.901,58.916 ; pad.0@83.446,56.449 cw(c83.048,55.892) 83.709,55.715 cw(c84.794,55.424) pad.0@84.247,56.405 ; pad.0@83.525,56.4 cw(c83.042,55.504) 84.025,55.767 cw(c84.602,55.921) pad.0@84.283,56.426 ; pad.0@83.564,54.838 ccw(c82.845,55.556) 83.861,55.556 ; pad.0@83.564,56.741 cw(c82.845,56.023) 83.861,56.023 ; pad.0@83.564,57.378 ccw(c82.75,58.191) 83.901,58.191 ; pad.0@83.62,56.693 cw(c83.316,56.268) 83.821,56.132 ; pad.0@83.861,54.58 pad.0@83.861,57.12 ; pad.0@83.861,55.199 cw(c85.742,55.199) pad.0@84.412,56.529 ; 83.861,55.656 ccw(c85.018,55.656) pad.0@84.2,54.838 ; 83.861,55.924 cw(c85.018,55.924) pad.0@84.2,56.741 ; pad.0@83.861,56.38 ccw(c85.742,56.38) pad.0@84.412,55.05 ; 83.901,58.1 ccw(c84.923,58.1) pad.0@84.2,57.378 ; 83.901,58.825 ccw(c85.647,58.825) pad.0@84.412,57.59
  Bottom w0.3: pad.0@83.351,55.05 ccw(c82.121,56.281) pad.0@83.861,56.281 ; pad.0@83.351,56.529 cw(c82.121,55.299) pad.0@83.861,55.299 ; pad.0@83.446,56.449 cw(c83.048,55.892) 83.709,55.715 cw(c84.794,55.424) pad.0@84.247,56.405 ; pad.0@83.525,56.4 cw(c83.042,55.504) 84.025,55.767 cw(c84.602,55.921) pad.0@84.283,56.426 ; pad.0@83.564,54.838 ccw(c82.845,55.556) 83.861,55.556 ; pad.0@83.564,56.741 cw(c82.845,56.023) 83.861,56.023 ; pad.0@83.62,56.693 cw(c83.316,56.268) 83.821,56.132 ; pad.0@83.861,54.58 pad.0@83.861,57.12 ; pad.0@83.861,55.199 cw(c85.742,55.199) pad.0@84.412,56.529 ; 83.861,55.656 ccw(c85.018,55.656) pad.0@84.2,54.838 ; 83.861,55.924 cw(c85.018,55.924) pad.0@84.2,56.741 ; pad.0@83.861,56.38 ccw(c85.742,56.38) pad.0@84.412,55.05
PC10: pad.0@81.189,65.279 pad.0@81.342,54.52 pad.0@81.342,57.06 U1.N12 | length 51.3
  Top w0.3: pad.0@80.811,55.05 ccw(c79.508,56.353) pad.0@81.351,56.353 ; pad.0@80.811,56.529 cw(c79.508,55.226) pad.0@81.351,55.226 ; pad.0@80.811,57.59 ccw(c79.508,58.893) 81.351,58.893 ; pad.0@80.931,56.432 cw(c80.591,55.913) 81.19,55.753 cw(c82.201,55.482) pad.0@81.701,56.401 ; pad.0@80.941,64.981 cw(c80.35,64.39) 81.186,64.39 ; pad.0@80.941,65.576 ccw(c80.35,66.167) 81.186,66.167 ; pad.0@80.979,56.403 cw(c80.449,55.445) 81.506,55.729 cw(c82.144,55.9) pad.0@81.768,56.443 ; U1.N12@81.009,67.193 cw(c80.583,66.766) 81.186,66.766 cw(c81.79,66.766) U1.N12@81.363,67.193 ; pad.0@81.024,54.838 ccw(c80.233,55.629) 81.351,55.629 ; pad.0@81.024,56.741 cw(c80.233,55.95) 81.351,55.95 ; pad.0@81.024,57.378 ccw(c80.233,58.169) 81.351,58.169 ; pad.0@81.095,56.683 cw(c80.83,56.278) 81.298,56.153 ; 81.186,64.377 cw(c82.04,64.377) pad.0@81.436,64.981 ; 81.186,66.18 ccw(c82.04,66.18) pad.0@81.436,65.576 ; U1.N12@81.186,67.77 81.186,59.214 81.351,59.049 pad.0@81.351,54.55 ; pad.0@81.351,55.272 cw(c83.13,55.272) pad.0@81.872,56.529 ; 81.351,55.583 ccw(c82.405,55.583) pad.0@81.66,54.838 ; 81.351,55.996 cw(c82.405,55.996) pad.0@81.66,56.741 ; pad.0@81.351,56.307 ccw(c83.13,56.307) pad.0@81.872,55.05 ; 81.351,58.123 ccw(c82.405,58.123) pad.0@81.66,57.378 ; 81.351,58.847 ccw(c83.13,58.847) pad.0@81.872,57.59 ; 81.396,56.14 cw(c81.887,56.272) pad.0@81.598,56.69
  Bottom w0.3: pad.0@80.811,55.05 ccw(c79.508,56.353) pad.0@81.351,56.353 ; pad.0@80.811,56.529 cw(c79.508,55.226) pad.0@81.351,55.226 ; pad.0@80.931,56.432 cw(c80.591,55.913) 81.19,55.753 cw(c82.201,55.482) pad.0@81.701,56.401 ; pad.0@80.979,56.403 cw(c80.449,55.445) 81.506,55.729 cw(c82.144,55.9) pad.0@81.768,56.443 ; pad.0@81.024,54.838 ccw(c80.233,55.629) 81.351,55.629 ; pad.0@81.024,56.741 cw(c80.233,55.95) 81.351,55.95 ; pad.0@81.095,56.683 cw(c80.83,56.278) 81.298,56.153 ; pad.0@81.351,54.55 pad.0@81.351,57.09 ; pad.0@81.351,55.272 cw(c83.13,55.272) pad.0@81.872,56.529 ; 81.351,55.583 ccw(c82.405,55.583) pad.0@81.66,54.838 ; 81.351,55.996 cw(c82.405,55.996) pad.0@81.66,56.741 ; pad.0@81.351,56.307 ccw(c83.13,56.307) pad.0@81.872,55.05 ; 81.396,56.14 cw(c81.887,56.272) pad.0@81.598,56.69
PC11: pad.0@78.802,54.52 pad.0@78.802,57.06 pad.0@79.919,65.279 U1.N13 | length 51.7
  Top w0.3: pad.0@78.271,55.05 ccw(c76.968,56.353) pad.0@78.811,56.353 ; pad.0@78.271,56.529 cw(c76.968,55.226) pad.0@78.811,55.226 ; pad.0@78.271,57.59 ccw(c76.968,58.893) 78.811,58.893 ; pad.0@78.391,56.432 cw(c78.051,55.913) 78.65,55.753 cw(c79.661,55.482) pad.0@79.161,56.401 ; pad.0@78.439,56.403 cw(c77.909,55.445) 78.966,55.729 cw(c79.604,55.9) pad.0@79.228,56.443 ; pad.0@78.484,54.838 ccw(c77.693,55.629) 78.811,55.629 ; pad.0@78.484,56.741 cw(c77.693,55.95) 78.811,55.95 ; pad.0@78.484,57.378 ccw(c77.693,58.169) 78.811,58.169 ; pad.0@78.555,56.683 cw(c78.29,56.278) 78.758,56.153 ; pad.0@78.811,54.55 78.811,60.61 79.916,61.715 U1.N13@79.916,67.77 ; pad.0@78.811,55.272 cw(c80.59,55.272) pad.0@79.332,56.529 ; 78.811,55.583 ccw(c79.865,55.583) pad.0@79.12,54.838 ; 78.811,55.996 cw(c79.865,55.996) pad.0@79.12,56.741 ; pad.0@78.811,56.307 ccw(c80.59,56.307) pad.0@79.332,55.05 ; 78.811,58.123 ccw(c79.865,58.123) pad.0@79.12,57.378 ; 78.811,58.847 ccw(c80.59,58.847) pad.0@79.332,57.59 ; 78.856,56.14 cw(c79.347,56.272) pad.0@79.058,56.69 ; pad.0@79.671,64.981 cw(c79.08,64.39) 79.916,64.39 ; pad.0@79.671,65.576 ccw(c79.08,66.167) 79.916,66.167 ; U1.N13@79.739,67.193 cw(c79.313,66.766) 79.916,66.766 cw(c80.52,66.766) U1.N13@80.093,67.193 ; 79.916,64.377 cw(c80.77,64.377) pad.0@80.166,64.981 ; 79.916,66.18 ccw(c80.77,66.18) pad.0@80.166,65.576
  Bottom w0.3: pad.0@78.271,55.05 ccw(c76.968,56.353) pad.0@78.811,56.353 ; pad.0@78.271,56.529 cw(c76.968,55.226) pad.0@78.811,55.226 ; pad.0@78.391,56.432 cw(c78.051,55.913) 78.65,55.753 cw(c79.661,55.482) pad.0@79.161,56.401 ; pad.0@78.439,56.403 cw(c77.909,55.445) 78.966,55.729 cw(c79.604,55.9) pad.0@79.228,56.443 ; pad.0@78.484,54.838 ccw(c77.693,55.629) 78.811,55.629 ; pad.0@78.484,56.741 cw(c77.693,55.95) 78.811,55.95 ; pad.0@78.555,56.683 cw(c78.29,56.278) 78.758,56.153 ; pad.0@78.811,54.55 pad.0@78.811,57.09 ; pad.0@78.811,55.272 cw(c80.59,55.272) pad.0@79.332,56.529 ; 78.811,55.583 ccw(c79.865,55.583) pad.0@79.12,54.838 ; 78.811,55.996 cw(c79.865,55.996) pad.0@79.12,56.741 ; pad.0@78.811,56.307 ccw(c80.59,56.307) pad.0@79.332,55.05 ; 78.856,56.14 cw(c79.347,56.272) pad.0@79.058,56.69
PC12: pad.0@76.262,54.52 pad.0@76.262,57.06 pad.0@78.646,65.279 U1.N14 | length 51.1
  Top w0.3: pad.0@75.731,55.05 ccw(c74.549,56.232) pad.0@76.221,56.232 ; pad.0@75.731,56.529 cw(c74.549,55.347) pad.0@76.221,55.347 ; pad.0@75.731,57.59 ccw(c74.599,58.723) 76.201,58.723 ; pad.0@75.81,56.461 cw(c75.37,55.878) 76.076,55.689 cw(c77.21,55.385) pad.0@76.631,56.407 ; pad.0@75.91,56.397 cw(c75.457,55.542) 76.391,55.793 cw(c76.929,55.937) pad.0@76.645,56.415 ; pad.0@75.944,54.838 ccw(c75.273,55.508) 76.221,55.508 ; pad.0@75.944,56.741 cw(c75.273,56.071) 76.221,56.071 ; pad.0@75.944,57.378 ccw(c75.323,57.998) 76.201,57.998 ; pad.0@75.991,56.7 cw(c75.659,56.261) 76.191,56.119 ; 76.201,58.294 ccw(c77.496,58.294) pad.0@76.58,57.378 ; 76.201,59.018 ccw(c78.22,59.018) pad.0@76.792,57.59 ; pad.0@76.221,54.58 pad.0@76.221,57.12 ; pad.0@76.221,55.151 cw(c78.17,55.151) pad.0@76.792,56.529 ; 76.221,55.704 ccw(c77.446,55.704) pad.0@76.58,54.838 ; 76.221,55.875 cw(c77.446,55.875) pad.0@76.58,56.741 ; pad.0@76.221,56.428 ccw(c78.17,56.428) pad.0@76.792,55.05 ; pad.0@76.271,57.09 76.201,57.16 76.201,59.669 78.646,62.115 pad.0@78.646,65.279 U1.N14@78.646,67.77 ; pad.0@78.399,64.981 cw(c77.801,64.384) 78.646,64.384 cw(c79.491,64.384) pad.0@78.894,64.981 ; pad.0@78.399,65.576 ccw(c77.801,66.173) 78.646,66.173 ccw(c79.491,66.173) pad.0@78.894,65.576 ; U1.N14@78.469,67.193 cw(c78.043,66.766) 78.646,66.766 cw(c79.25,66.766) U1.N14@78.823,67.193
  Bottom w0.3: pad.0@75.731,55.05 ccw(c74.549,56.232) pad.0@76.221,56.232 ; pad.0@75.731,56.529 cw(c74.549,55.347) pad.0@76.221,55.347 ; pad.0@75.81,56.461 cw(c75.37,55.878) 76.076,55.689 cw(c77.21,55.385) pad.0@76.631,56.407 ; pad.0@75.91,56.397 cw(c75.457,55.542) 76.391,55.793 cw(c76.929,55.937) pad.0@76.645,56.415 ; pad.0@75.944,54.838 ccw(c75.273,55.508) 76.221,55.508 ; pad.0@75.944,56.741 cw(c75.273,56.071) 76.221,56.071 ; pad.0@75.991,56.7 cw(c75.659,56.261) 76.191,56.119 ; pad.0@76.221,54.58 pad.0@76.221,57.12 ; pad.0@76.221,55.151 cw(c78.17,55.151) pad.0@76.792,56.529 ; 76.221,55.704 ccw(c77.446,55.704) pad.0@76.58,54.838 ; 76.221,55.875 cw(c77.446,55.875) pad.0@76.58,56.741 ; pad.0@76.221,56.428 ccw(c78.17,56.428) pad.0@76.792,55.05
